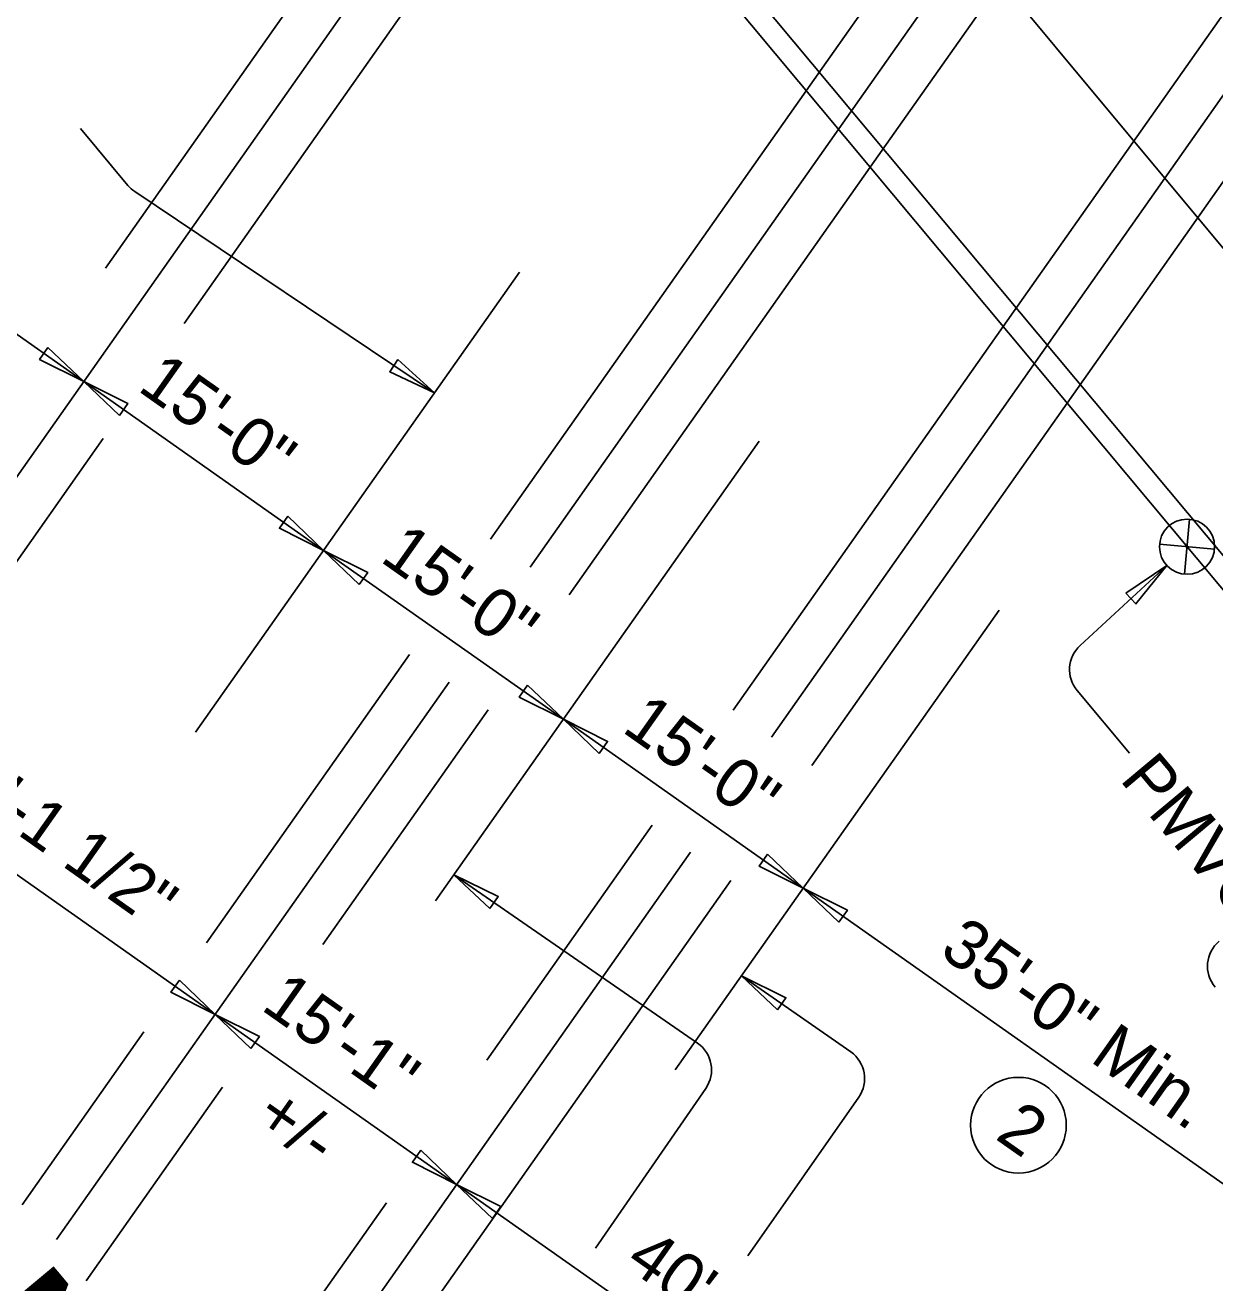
# Model space of a CAD drawing. Extents: x 2042995 to 2043795, y 305365 to 306249.
# Drawn here: x 2043429.9 to 2043490.7, y 305804 to 305868.4 of the extents above; entities that cross this region are included whole.
import ezdxf

# ---------------------------------------------------------------- set-up
doc = ezdxf.new("R2010")
doc.units = 0
for name, color, linetype in [('BR_AUTO DIMENSION', 7, 'Continuous'), ('BR_CENTER LINES', 7, 'Continuous'), ('BR_CONCRETE', 7, 'Continuous'), ('BR_EXISTING_BRIDGE', 7, 'Continuous'), ('BR_STRUCTURAL STEEL', 7, 'Continuous'), ('BR_TEXT', 7, 'Continuous')]:
    doc.layers.add(name, color=color, linetype=linetype)

msp = doc.modelspace()

# ---------------------------------------------------------------- linework, layer by layer
at = {"layer": 'BR_AUTO DIMENSION'}
for p, q in [((2043408.363, 305867.406), (2043432.893, 305850.135)), ((2043432.722, 305863.074), (2043435.154, 305860.162)), ((2043435.503, 305859.848), (2043450.824, 305849.547)), ((2043432.893, 305850.135), (2043445.158, 305841.5)), ((2043489.444, 305843.091), (2043489.192, 305840.284)), ((2043445.158, 305841.5), (2043457.423, 305832.864)), ((2043487.914, 305841.814), (2043490.722, 305841.561)), ((2043483.845, 305836.632), (2043488.282, 305840.731)), ((2043486.372, 305831.136), (2043483.697, 305834.339)), ((2043457.423, 305832.864), (2043469.688, 305824.229)), ((2043419.888, 305831.664), (2043439.617, 305817.773)), ((2043464.28, 305816.312), (2043451.825, 305824.914)), ((2043469.688, 305824.229), (2043498.306, 305804.08)), ((2043472.116, 305815.857), (2043466.537, 305819.754)), ((2043439.617, 305817.773), (2043451.964, 305809.079)), ((2043459.061, 305805.823), (2043464.704, 305813.993)), ((2043466.864, 305805.425), (2043472.529, 305813.536)), ((2043451.964, 305809.079), (2043485.301, 305785.608))]:
    msp.add_line(p, q, dxfattribs=at)
for points in [[(2043431.065, 305851.881), (2043432.893, 305850.135), (2043430.633, 305851.268)], [(2043448.958, 305851.253), (2043450.824, 305849.547), (2043448.54, 305850.63)], [(2043434.722, 305848.39), (2043432.893, 305850.135), (2043435.153, 305849.003)], [(2043443.33, 305843.246), (2043445.158, 305841.5), (2043442.898, 305842.633)], [(2043446.987, 305839.754), (2043445.158, 305841.5), (2043447.418, 305840.367)], [(2043486.192, 305839.31), (2043488.282, 305840.731), (2043486.701, 305838.759)], [(2043455.595, 305834.61), (2043457.423, 305832.864), (2043455.163, 305833.997)], [(2043459.251, 305831.119), (2043457.423, 305832.864), (2043459.683, 305831.732)], [(2043467.86, 305825.975), (2043469.688, 305824.229), (2043467.428, 305825.362)], [(2043453.669, 305823.185), (2043451.825, 305824.914), (2043454.096, 305823.802)], [(2043471.516, 305822.483), (2043469.688, 305824.229), (2043471.948, 305823.096)], [(2043468.372, 305818.015), (2043466.537, 305819.754), (2043468.801, 305818.63)], [(2043437.789, 305819.519), (2043439.617, 305817.773), (2043437.357, 305818.906)], [(2043441.445, 305816.027), (2043439.617, 305817.773), (2043441.877, 305816.64)], [(2043450.136, 305810.825), (2043451.964, 305809.079), (2043449.704, 305810.212)], [(2043453.793, 305807.334), (2043451.964, 305809.079), (2043454.224, 305807.947)]]:
    msp.add_lwpolyline(points, close=True, dxfattribs=at)
msp.add_circle((2043489.318, 305841.687), 1.41, dxfattribs=at)
for centre, start, end in [((2043436.433, 305861.231), 219.86836, 236.08599), ((2043484.976, 305835.408), 132.73407, 219.86836), ((2043492.029, 305820.243), 129.86836, 219.86836), ((2043463.332, 305814.94), 325.36669, 55.36669), ((2043471.162, 305814.49), 325.0694, 55.0694)]:
    msp.add_arc(centre, 1.667, start, end, dxfattribs=at)
at = {"layer": 'BR_CENTER LINES'}
for points in [[(2043414.237, 305823.638), (2043467.578, 305899.398), (2043511.813, 305962.173)], [(2043455.72, 305840.641), (2043487.579, 305885.883), (2043531.514, 305948.302)], [(2043468.058, 305831.954), (2043499.952, 305877.288), (2043543.878, 305939.594)], [(2043438.618, 305832.212), (2043455.178, 305855.732)], [(2043450.883, 305823.576), (2043467.44, 305847.091)], [(2043463.148, 305814.941), (2043479.702, 305838.451)], [(2043431.508, 305806.258), (2043451.577, 305834.758)], [(2043431.537, 305780.045), (2043463.917, 305826.069)]]:
    msp.add_lwpolyline(points, dxfattribs=at)
at = {"layer": 'BR_CONCRETE'}
for p, q in [((2043378.474, 305974.405), (2043563.733, 305752.588)), ((2043391.965, 305960.007), (2043523.577, 305802.424))]:
    msp.add_line(p, q, dxfattribs=at)
msp.add_spline([(2043139.109, 306017.548), (2043148.199, 306007.16), (2043160.233, 305993.368), (2043172.245, 305979.557), (2043184.234, 305965.727), (2043196.201, 305951.879), (2043208.145, 305938.012), (2043220.067, 305924.126), (2043231.966, 305910.221), (2043243.843, 305896.297), (2043255.698, 305882.355), (2043267.529, 305868.394), (2043279.339, 305854.414), (2043291.126, 305840.415), (2043302.89, 305826.398), (2043314.632, 305812.361), (2043326.352, 305798.306), (2043338.049, 305784.233), (2043349.724, 305770.14), (2043361.376, 305756.029), (2043373.005, 305741.899), (2043384.613, 305727.75), (2043396.197, 305713.582), (2043407.76, 305699.396), (2043419.299, 305685.191), (2043430.817, 305670.967), (2043442.311, 305656.724), (2043453.784, 305642.463), (2043465.234, 305628.182), (2043476.661, 305613.883), (2043488.066, 305599.566), (2043499.448, 305585.229), (2043510.808, 305570.874), (2043522.146, 305556.5), (2043533.461, 305542.107), (2043544.753, 305527.695), (2043547.219, 305524.543)], degree=3, dxfattribs=at)
at = {"layer": 'BR_EXISTING_BRIDGE'}
msp.add_lwpolyline([(2043457.568, 305934.733), (2043443.332, 305914.368), (2043521.862, 305820.103), (2043536.154, 305840.416), (2043457.568, 305934.733)], dxfattribs=at)
at = {"layer": 'BR_STRUCTURAL STEEL'}
for p, q in [((2043469.845, 305865.004), (2043497.407, 305904.152)), ((2043500.673, 305900.242), (2043473.111, 305861.093)), ((2043479.918, 305852.943), (2043507.484, 305892.087)), ((2043510.75, 305888.177), (2043483.183, 305849.033)), ((2043434.005, 305855.931), (2043453.868, 305884.133)), ((2043457.134, 305880.223), (2043438.028, 305853.097)), ((2043453.696, 305842.066), (2043469.845, 305865.004)), ((2043473.111, 305861.093), (2043457.72, 305839.233)), ((2043466.104, 305833.328), (2043479.918, 305852.943)), ((2043483.183, 305849.033), (2043470.128, 305830.495)), ((2043433.887, 305847.217), (2043423.377, 305832.295)), ((2043439.169, 305821.433), (2043449.554, 305836.183)), ((2043453.578, 305833.349), (2043445.126, 305821.344)), ((2043453.508, 305815.441), (2043461.961, 305827.446)), ((2043465.986, 305824.613), (2043433.199, 305778.055)), ((2043429.742, 305808.043), (2043435.967, 305816.884)), ((2043439.991, 305814.051), (2043433.021, 305804.152)), ((2043429.933, 305781.966), (2043448.372, 305808.149))]:
    msp.add_line(p, q, dxfattribs=at)
at = {"layer": 'BR_TEXT'}
msp.add_circle((2043480.695, 305812.109), 2.447, dxfattribs=at)

# ---------------------------------------------------------------- texts
at = {"layer": 'BR_AUTO DIMENSION'}
msp.add_text('246\'-0" Continuous Prestressed Concrete Beam (FIB-54) Bridge Out-To-Out', height=2.5, rotation=309.86836, dxfattribs=at).set_placement((2043360.493, 305856.957))
at = {"layer": 'BR_TEXT'}
for s, height, rotation, p in [('15\'-0"', 2.5, 324.8166, (2043435.584, 305849.71)), ('15\'-0"', 2.5, 324.8166, (2043447.984, 305840.98)), ('15\'-0"', 2.5, 324.8166, (2043460.353, 305832.271)), ('24\'-1 1/2"', 2.5, 324.8166, (2043424.959, 305830.174)), ('PMVC', 2.5, 309.86836, (2043485.828, 305829.777)), ('35\'-0" Min.', 2.5, 324.8166, (2043476.575, 305820.85)), ('PLAN', 8.1251, 309.86836, (2043411.383, 305816.135)), ('15\'-1"', 2.5, 324.8166, (2043441.896, 305818.055)), ('+/-', 2.5, 324.8166, (2043441.505, 305812.213)), ('2', 2.5, 324.85143, (2043479.446, 305811.449)), ('40\'-9 1/2" Min.', 2.5, 324.8166, (2043460.499, 305804.923))]:
    msp.add_text(s, height=height, rotation=rotation, dxfattribs=at).set_placement(p)

doc.saveas('drawing.dxf')
